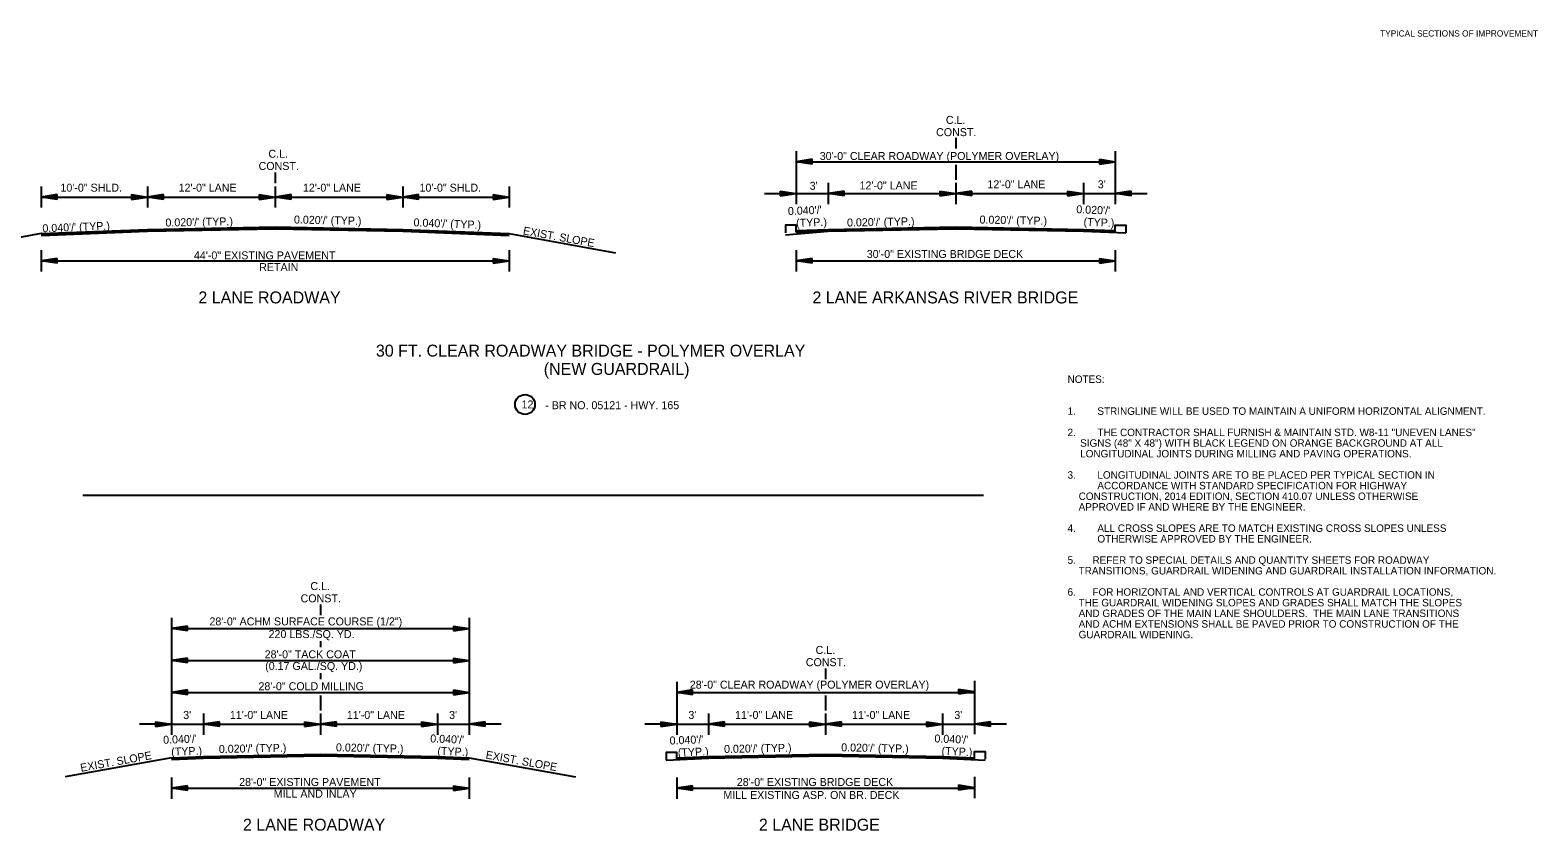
# Model space of a CAD drawing. Extents: x 545241 to 1930787, y -1971772 to 596640.
# Drawn here: x 546838 to 548255, y -1953338 to -1952586 of the extents above; entities that cross this region are included whole.
import ezdxf

# ---------------------------------------------------------------- set-up
doc = ezdxf.new("R2010")
doc.units = 0
for name, color, linetype in [('R_Border', 7, 'Continuous'), ('R_Border Notes', 7, 'Continuous'), ('R_Border Prem', 7, 'Continuous'), ('R_Draft', 7, 'Continuous')]:
    doc.layers.add(name, color=color, linetype=linetype)

# ---------------------------------------------------------------- blocks, each defined once
blk = doc.blocks.new('ARROW')
at = {"layer": 'R_Draft'}
for p, q in [((-2, 0.3), (0, 0)), ((-2, 0.3), (-2, -0.3)), ((-2, 0.25), (-0.334, 0)), ((-2, 0.199), (-0.678, 0)), ((-2, 0.149), (-1.011, 0)), ((-2, 0.097), (-1.35, 0)), ((-2, 0.047), (-1.684, 0)), ((-2, -0.3), (0, 0)), ((-2, -0.098), (-1.35, 0)), ((-2, -0.199), (-0.678, 0)), ((-2, -0.25), (-0.334, 0)), ((-2, -0.149), (-1.011, 0)), ((-2, -0.047), (-1.684, 0))]:
    blk.add_line(p, q, dxfattribs=at)
blk = doc.blocks.new('BPPOLY')
at = {"layer": 'R_Border'}
blk.add_circle((0, 0), 9.34, dxfattribs=at)

msp = doc.modelspace()

# ---------------------------------------------------------------- linework, layer by layer
at = {"layer": 'R_Border'}
for p, q in [((547707.9, -1952687.1), (547707.9, -1952697.1)), ((547557.9, -1952699.6), (547557.9, -1952749.6)), ((547557.9, -1952709.6), (547857.9, -1952709.6)), ((547857.9, -1952699.6), (547857.9, -1952749.6)), ((547067.9, -1952719.8), (547067.9, -1952729.8)), ((547707.9, -1952712.6), (547707.9, -1952726.6)), ((546847.9, -1952732.8), (546847.9, -1952752.8)), ((546947.9, -1952732.8), (546947.9, -1952752.8)), ((547067.9, -1952732.8), (547067.9, -1952752.8)), ((547187.9, -1952732.8), (547187.9, -1952752.8)), ((547287.9, -1952732.8), (547287.9, -1952752.8)), ((547587.9, -1952729.6), (547587.9, -1952749.6)), ((547707.9, -1952729.6), (547707.9, -1952749.6)), ((547827.9, -1952729.6), (547827.9, -1952749.6)), ((546847.9, -1952742.8), (547287.9, -1952742.8)), ((547527.9, -1952739.6), (547887.9, -1952739.6)), ((546847.9, -1952777.2), (546747.9, -1952795.2)), ((547287.9, -1952777.2), (547387.9, -1952795.2)), ((546847.9, -1952792.8), (546847.9, -1952812.8)), ((547287.9, -1952792.8), (547287.9, -1952812.8)), ((547557.9, -1952792.8), (547557.9, -1952812.8)), ((547857.9, -1952792.8), (547857.9, -1952812.8)), ((546847.9, -1952802.8), (547287.9, -1952802.8)), ((547557.9, -1952802.8), (547857.9, -1952802.8)), ((546887.2, -1953022.9), (547733.9, -1953022.9)), ((547110.5, -1953125.8), (547110.5, -1953135.8)), ((546970.5, -1953138.3), (546970.5, -1953248.3)), ((546970.5, -1953148.3), (547250.5, -1953148.3)), ((547250.5, -1953138.3), (547250.5, -1953248.3)), ((547110.5, -1953160.3), (547110.5, -1953165.8)), ((546970.5, -1953178.3), (547250.5, -1953178.3)), ((547110.5, -1953190.3), (547110.5, -1953195.8)), ((547585.5, -1953185.8), (547585.5, -1953195.8)), ((547445.5, -1953198.3), (547445.5, -1953248.3)), ((547725.5, -1953197.6), (547725.5, -1953247.6)), ((546970.5, -1953208.3), (547250.5, -1953208.3)), ((547110.5, -1953211.3), (547110.5, -1953225.3)), ((547445.5, -1953208.3), (547725.5, -1953208.3)), ((547585.5, -1953211.3), (547585.5, -1953225.3)), ((547000.5, -1953228.3), (547000.5, -1953248.3)), ((547110.5, -1953228.3), (547110.5, -1953248.3)), ((547220.5, -1953228.3), (547220.5, -1953248.3)), ((547475.5, -1953228.3), (547475.5, -1953248.3)), ((547585.5, -1953228.3), (547585.5, -1953248.3)), ((547695.5, -1953228.3), (547695.5, -1953248.3)), ((546970.5, -1953238.3), (546940.5, -1953238.3)), ((546970.5, -1953238.3), (547250.5, -1953238.3)), ((547280.5, -1953238.3), (547250.5, -1953238.3)), ((547445.5, -1953238.3), (547415.5, -1953238.3)), ((547445.5, -1953238.3), (547725.5, -1953238.3)), ((547755.5, -1953238.3), (547725.5, -1953238.3)), ((546970.5, -1953269.7), (546870.5, -1953287.7)), ((547250.5, -1953269.7), (547350.5, -1953287.7)), ((546970.5, -1953288.3), (546970.5, -1953308.3)), ((547250.5, -1953288.3), (547250.5, -1953308.3)), ((547445.5, -1953288.3), (547445.5, -1953308.3)), ((547725.5, -1953287.6), (547725.5, -1953307.6)), ((546970.5, -1953298.3), (547250.5, -1953298.3)), ((547445.5, -1953298.3), (547725.5, -1953298.3))]:
    msp.add_line(p, q, dxfattribs=at)
for points in [[(546847.9, -1952777.2), (546947.9, -1952773.2), (547067.9, -1952770.8), (547187.9, -1952773.2), (547287.9, -1952777.2)], [(546847.9, -1952777.5), (546947.9, -1952773.5), (547067.9, -1952771.1), (547187.9, -1952773.5), (547287.9, -1952777.5)], [(546847.9, -1952777.8), (546947.9, -1952773.8), (547067.9, -1952771.4), (547187.9, -1952773.8), (547287.9, -1952777.8)], [(546847.9, -1952778.1), (546947.9, -1952774.1), (547067.9, -1952771.7), (547187.9, -1952774.1), (547287.9, -1952778.1)], [(546847.9, -1952778.4), (546947.9, -1952774.4), (547067.9, -1952772), (547187.9, -1952774.4), (547287.9, -1952778.4)], [(546847.9, -1952778.7), (546947.9, -1952774.7), (547067.9, -1952772.3), (547187.9, -1952774.7), (547287.9, -1952778.7)], [(546847.9, -1952779), (546947.9, -1952775), (547067.9, -1952772.6), (547187.9, -1952775), (547287.9, -1952779)], [(547557.9, -1952775.9), (547557.9, -1952769.4), (547547.9, -1952769.4), (547547.9, -1952776.6)], [(547547.9, -1952778.4), (547587.9, -1952775), (547707.9, -1952772.6), (547827.9, -1952775), (547867.9, -1952776.6)], [(547557.9, -1952774.4), (547587.9, -1952773.2), (547707.9, -1952770.8), (547827.9, -1952773.2), (547857.9, -1952774.4)], [(547557.9, -1952774.7), (547587.9, -1952773.5), (547707.9, -1952771.1), (547827.9, -1952773.5), (547857.9, -1952774.7)], [(547557.9, -1952775), (547587.9, -1952773.8), (547707.9, -1952771.4), (547827.9, -1952773.8), (547857.9, -1952775)], [(547557.9, -1952775.3), (547587.9, -1952774.1), (547707.9, -1952771.7), (547827.9, -1952774.1), (547857.9, -1952775.3)], [(547557.9, -1952775.6), (547587.9, -1952774.4), (547707.9, -1952772), (547827.9, -1952774.4), (547857.9, -1952775.6)], [(547557.9, -1952775.9), (547587.9, -1952774.7), (547707.9, -1952772.3), (547827.9, -1952774.7), (547857.9, -1952775.9)], [(547857.9, -1952776.6), (547857.9, -1952769.4), (547867.9, -1952769.4), (547867.9, -1952776.6)], [(546970.5, -1953269.7), (547000.5, -1953268.5), (547110.5, -1953266.3), (547220.5, -1953268.5), (547250.5, -1953269.7)], [(546970.5, -1953270), (547000.5, -1953268.8), (547110.5, -1953266.6), (547220.5, -1953268.8), (547250.5, -1953270)], [(546970.5, -1953270.3), (547000.5, -1953269.1), (547110.5, -1953266.9), (547220.5, -1953269.1), (547250.5, -1953270.3)], [(546970.5, -1953270.6), (547000.5, -1953269.4), (547110.5, -1953267.2), (547220.5, -1953269.4), (547250.5, -1953270.6)], [(546970.5, -1953270.9), (547000.5, -1953269.7), (547110.5, -1953267.5), (547220.5, -1953269.7), (547250.5, -1953270.9)], [(546970.5, -1953271.2), (547000.5, -1953270), (547110.5, -1953267.8), (547220.5, -1953270), (547250.5, -1953271.2)], [(546970.5, -1953271.5), (547000.5, -1953270.3), (547110.5, -1953268.1), (547220.5, -1953270.3), (547250.5, -1953271.5)], [(547445.5, -1953271.2), (547445.5, -1953264.7), (547435.5, -1953264.7), (547435.5, -1953271.9)], [(547435.5, -1953271.9), (547475.5, -1953270.3), (547585.5, -1953268.1), (547695.5, -1953270.3), (547735.5, -1953271.9)], [(547445.5, -1953269.7), (547475.5, -1953268.5), (547585.5, -1953266.3), (547695.5, -1953268.5), (547725.5, -1953269.7)], [(547445.5, -1953270), (547475.5, -1953268.8), (547585.5, -1953266.6), (547695.5, -1953268.8), (547725.5, -1953270)], [(547445.5, -1953270.3), (547475.5, -1953269.1), (547585.5, -1953266.9), (547695.5, -1953269.1), (547725.5, -1953270.3)], [(547445.5, -1953270.6), (547475.5, -1953269.4), (547585.5, -1953267.2), (547695.5, -1953269.4), (547725.5, -1953270.6)], [(547445.5, -1953270.9), (547475.5, -1953269.7), (547585.5, -1953267.5), (547695.5, -1953269.7), (547725.5, -1953270.9)], [(547445.5, -1953271.2), (547475.5, -1953270), (547585.5, -1953267.8), (547695.5, -1953270), (547725.5, -1953271.2)], [(547725.5, -1953271.2), (547725.5, -1953264), (547735.5, -1953264), (547735.5, -1953271.2)]]:
    msp.add_lwpolyline(points, dxfattribs=at)

# ---------------------------------------------------------------- block references
at = {"layer": 'R_Border', "xscale": 7.5, "yscale": 7.5, "rotation": 180}
for p in [(547557.9, -1952709.6), (547587.9, -1952739.6), (547707.9, -1952739.6), (547857.9, -1952739.6), (546847.9, -1952742.8), (546947.9, -1952742.8), (547067.9, -1952742.8), (547187.9, -1952742.8), (546847.9, -1952802.8), (547557.9, -1952802.8), (546970.5, -1953148.3), (546970.5, -1953178.3), (546970.5, -1953208.3), (547445.5, -1953208.3), (547000.5, -1953238.3), (547110.5, -1953238.3), (547250.5, -1953238.3), (547475.5, -1953238.3), (547585.5, -1953238.3), (547725.5, -1953238.3), (546970.5, -1953298.3), (547445.5, -1953298.3)]:
    msp.add_blockref('ARROW', p, dxfattribs=at)
at = {"layer": 'R_Border', "xscale": 7.5, "yscale": 7.5}
for p in [(547857.9, -1952709.6), (547557.9, -1952739.6), (547707.9, -1952739.6), (547827.9, -1952739.6), (546947.9, -1952742.8), (547067.9, -1952742.8), (547187.9, -1952742.8), (547287.9, -1952742.8), (547287.9, -1952802.8), (547857.9, -1952802.8), (547250.5, -1953148.3), (547250.5, -1953178.3), (547250.5, -1953208.3), (547725.5, -1953207.6), (546970.5, -1953238.3), (547110.5, -1953238.3), (547220.5, -1953238.3), (547445.5, -1953238.3), (547585.5, -1953238.3), (547695.5, -1953238.3), (547250.5, -1953298.3), (547725.5, -1953297.6)]:
    msp.add_blockref('ARROW', p, dxfattribs=at)
at = {"layer": 'R_Border'}
msp.add_blockref('BPPOLY', (547302.9, -1952937.8), dxfattribs=at)

# ---------------------------------------------------------------- texts
for s, height, p in [('C.L.', 7.5, (547698.6, -1952674.1)), ('CONST.', 7.5, (547689.4, -1952685.6)), ('CONST.', 7.5, (547052.4, -1952717.4)), ('C.L.', 7.5, (547061.6, -1952705.9)), ('30\'-0" CLEAR ROADWAY (POLYMER OVERLAY)', 7.5, (547580, -1952708)), ('10\'-0" SHLD.', 7.5, (546866.1, -1952737.8)), ('12\'-0" LANE', 7.5, (546977.2, -1952737.8)), ('12\'-0" LANE', 7.5, (547094.1, -1952737.8)), ('10\'-0" SHLD.', 7.5, (547203.7, -1952737.8)), ("3'", 7.5, (547570.5, -1952736)), ('12\'-0" LANE', 7.5, (547617.4, -1952735.7)), ('12\'-0" LANE', 7.5, (547737.6, -1952734.6)), ("3'", 7.5, (547841.4, -1952734.6)), ('44\'-0" EXISTING PAVEMENT', 7.5, (546991.6, -1952801.4)), ('30\'-0" EXISTING BRIDGE DECK', 7.5, (547624.2, -1952800.1)), ('RETAIN', 7.5, (547053, -1952812.4)), ('2 LANE ROADWAY', 11.25, (546995.8, -1952842.8)), ('2 LANE ARKANSAS RIVER BRIDGE', 11.25, (547573.1, -1952842.8)), ('30 FT. CLEAR ROADWAY BRIDGE - POLYMER OVERLAY', 11.25, (547162.7, -1952892.8)), ('(NEW GUARDRAIL)', 11.25, (547320.5, -1952910)), ('12', 7.5, (547299.6, -1952941.5)), ('- BR NO. 05121 - HWY. 165', 7.5, (547321.9, -1952942.2)), ('C.L.', 7.5, (547101.1, -1953112.2)), ('CONST.', 7.5, (547091.9, -1953123.7)), ('28\'-0" ACHM SURFACE COURSE (1/2")', 7.5, (547006.2, -1953145.4)), ('220 LBS./SQ. YD.', 7.5, (547061.8, -1953157.3)), ('28\'-0" TACK COAT', 7.5, (547058.1, -1953176.3)), ('CONST.', 7.5, (547566.9, -1953183.7)), ('C.L.', 7.5, (547576.1, -1953172.2)), ('(0.17 GAL./SQ. YD.)', 7.5, (547058.6, -1953187.3)), ('28\'-0" COLD MILLING', 7.5, (547052.3, -1953206.3)), ('28\'-0" CLEAR ROADWAY (POLYMER OVERLAY)', 7.5, (547457.8, -1953204.8)), ("3'", 7.5, (546981.5, -1953233.3)), ('11\'-0" LANE', 7.5, (547025.4, -1953233.3)), ('11\'-0" LANE', 7.5, (547135.4, -1953233.3)), ("3'", 7.5, (547231.5, -1953233.3)), ("3'", 7.5, (547456.5, -1953233.3)), ('11\'-0" LANE', 7.5, (547500.4, -1953233.3)), ('11\'-0" LANE', 7.5, (547610.4, -1953233.3)), ("3'", 7.5, (547706.5, -1953233.3)), ('28\'-0" EXISTING PAVEMENT', 7.5, (547034.1, -1953296.3)), ('28\'-0" EXISTING BRIDGE DECK', 7.5, (547502, -1953296.3)), ('MILL AND INLAY', 7.5, (547066.6, -1953307.3)), ('2 LANE ROADWAY', 11.25, (547037.7, -1953338.3)), ('2 LANE BRIDGE', 11.25, (547522.8, -1953338.3))]:
    msp.add_text(s, height=height, dxfattribs=at).set_placement(p)
for s, rotation, p in [("0.040'/'", 2.2916, (547550.2, -1952759.8)), ("0.020'/' ", 357.7084, (547821.1, -1952758)), ("0.040'/' (TYP.)", 2.2916, (546849.3, -1952776)), ("0.020'/' (TYP.)", 1.1458, (546964.9, -1952770.6)), ("0.020'/' (TYP.)", 358.8542, (547085.6, -1952767.7)), ("0.040'/' (TYP.)", 357.7084, (547198, -1952770.3)), ('(TYP.)', 2.2916, (547557.9, -1952771)), ("0.020'/' (TYP.)", 1.1458, (547605.7, -1952770.6)), ("0.020'/' (TYP.)", 358.8542, (547730.2, -1952767.7)), ('(TYP.)', 357.7084, (547827.9, -1952769.8)), ('EXIST. SLOPE', 349.796, (547300.6, -1952777.9)), ("0.040'/'", 2.2916, (546962.8, -1953256.7)), ("0.040'/'", 357.7084, (547213.7, -1953255.3)), ("0.040'/'", 2.2916, (547439, -1953257.4)), ("0.040'/'", 357.7084, (547687.7, -1953255.3)), ('(TYP.)', 2.2916, (546970.4, -1953267.9)), ("0.020'/' (TYP.)", 1.1458, (547015.1, -1953265.3)), ("0.020'/' (TYP.)", 358.8542, (547125.1, -1953263.7)), ('(TYP.)', 357.7084, (547220.4, -1953267)), ('(TYP.)', 2.2916, (547446.7, -1953268.6)), ("0.020'/' (TYP.)", 1.1458, (547490.1, -1953265.3)), ("0.020'/' (TYP.)", 358.8542, (547600.1, -1953263.7)), ('(TYP.)', 357.7084, (547694.4, -1953267)), ('EXIST. SLOPE', 10.204, (546885.5, -1953283)), ('EXIST. SLOPE', 349.796, (547265.5, -1953270.4))]:
    msp.add_text(s, height=7.5, rotation=rotation, dxfattribs=at).set_placement(p)
at = {"layer": 'R_Border Notes'}
for s, p in [('NOTES: ', (547813, -1952917.5)), ('1.', (547813, -1952947.5)), ('STRINGLINE WILL BE USED TO MAINTAIN A UNIFORM HORIZONTAL ALIGNMENT.', (547841, -1952947.5)), ('2.', (547813, -1952967.5)), ('THE CONTRACTOR SHALL FURNISH & MAINTAIN STD. W8-11 "UNEVEN LANES" ', (547841, -1952967.5)), ('    SIGNS (48" X 48") WITH BLACK LEGEND ON ORANGE BACKGROUND AT ALL ', (547814.4, -1952977.5)), ('    LONGITUDINAL JOINTS DURING MILLING AND PAVING OPERATIONS.', (547814.4, -1952987.5)), ('3.', (547813, -1953007.5)), ('LONGITUDINAL JOINTS ARE TO BE PLACED PER TYPICAL SECTION IN ', (547841, -1953007.5)), ('    CONSTRUCTION, 2014 EDITION, SECTION 410.07 UNLESS OTHERWISE', (547813, -1953027.5)), ('ACCORDANCE WITH STANDARD SPECIFICATION FOR HIGHWAY', (547841, -1953017.5)), ('    APPROVED IF AND WHERE BY THE ENGINEER.', (547813, -1953037.5)), ('4.', (547813, -1953057.5)), ('ALL CROSS SLOPES ARE TO MATCH EXISTING CROSS SLOPES UNLESS ', (547841, -1953057.5)), ('OTHERWISE APPROVED BY THE ENGINEER.', (547841, -1953067.5)), ('5.      REFER TO SPECIAL DETAILS AND QUANTITY SHEETS FOR ROADWAY', (547813, -1953087.5)), ('    TRANSITIONS, GUARDRAIL WIDENING AND GUARDRAIL INSTALLATION INFORMATION.', (547813, -1953097.5)), ('6.      FOR HORIZONTAL AND VERTICAL CONTROLS AT GUARDRAIL LOCATIONS,', (547813, -1953117.5)), ('    THE GUARDRAIL WIDENING SLOPES AND GRADES SHALL MATCH THE SLOPES', (547813, -1953127.5)), ('    AND GRADES OF THE MAIN LANE SHOULDERS.  THE MAIN LANE TRANSITIONS', (547813, -1953137.5)), ('    AND ACHM EXTENSIONS SHALL BE PAVED PRIOR TO CONSTRUCTION OF THE', (547813, -1953147.5)), ('    GUARDRAIL WIDENING.', (547813, -1953157.5))]:
    msp.add_text(s, height=7, dxfattribs=at).set_placement(p)
at = {"layer": 'R_Border Prem'}
msp.add_text('TYPICAL SECTIONS OF IMPROVEMENT', height=5.862, rotation=360, dxfattribs=at).set_placement((548106.8, -1952592))
at = {"layer": 'R_Draft'}
msp.add_text('MILL EXISTING ASP. ON BR. DECK', height=7.5, dxfattribs=at).set_placement((547489.4, -1953308.5))

doc.saveas('drawing.dxf')
